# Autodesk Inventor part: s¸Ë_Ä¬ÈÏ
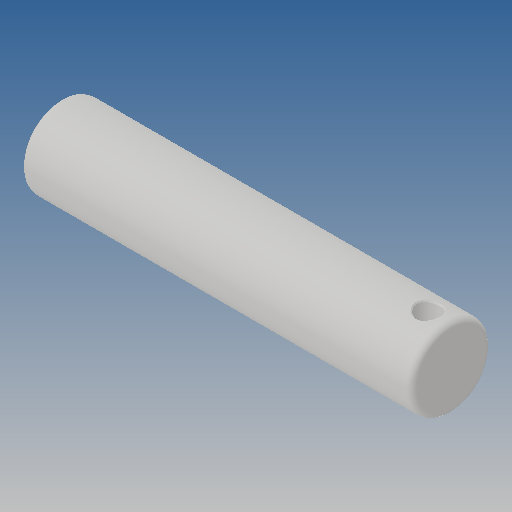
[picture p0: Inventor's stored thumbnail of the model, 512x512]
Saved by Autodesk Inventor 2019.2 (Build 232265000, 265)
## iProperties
Created: 2012-03
Part Number: s¸Ë_Ä¬ÈÏ
Material: Ogólny
Document SubType Name: Modeling
Designer: CADENGINEERING4
Density: 1 g/cm^3
Appearance: Domyślna
Author: CADENGINEERING4
Revision Number: ÈÎºÎ
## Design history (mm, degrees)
feature "NONE"
node "Bryła1"
